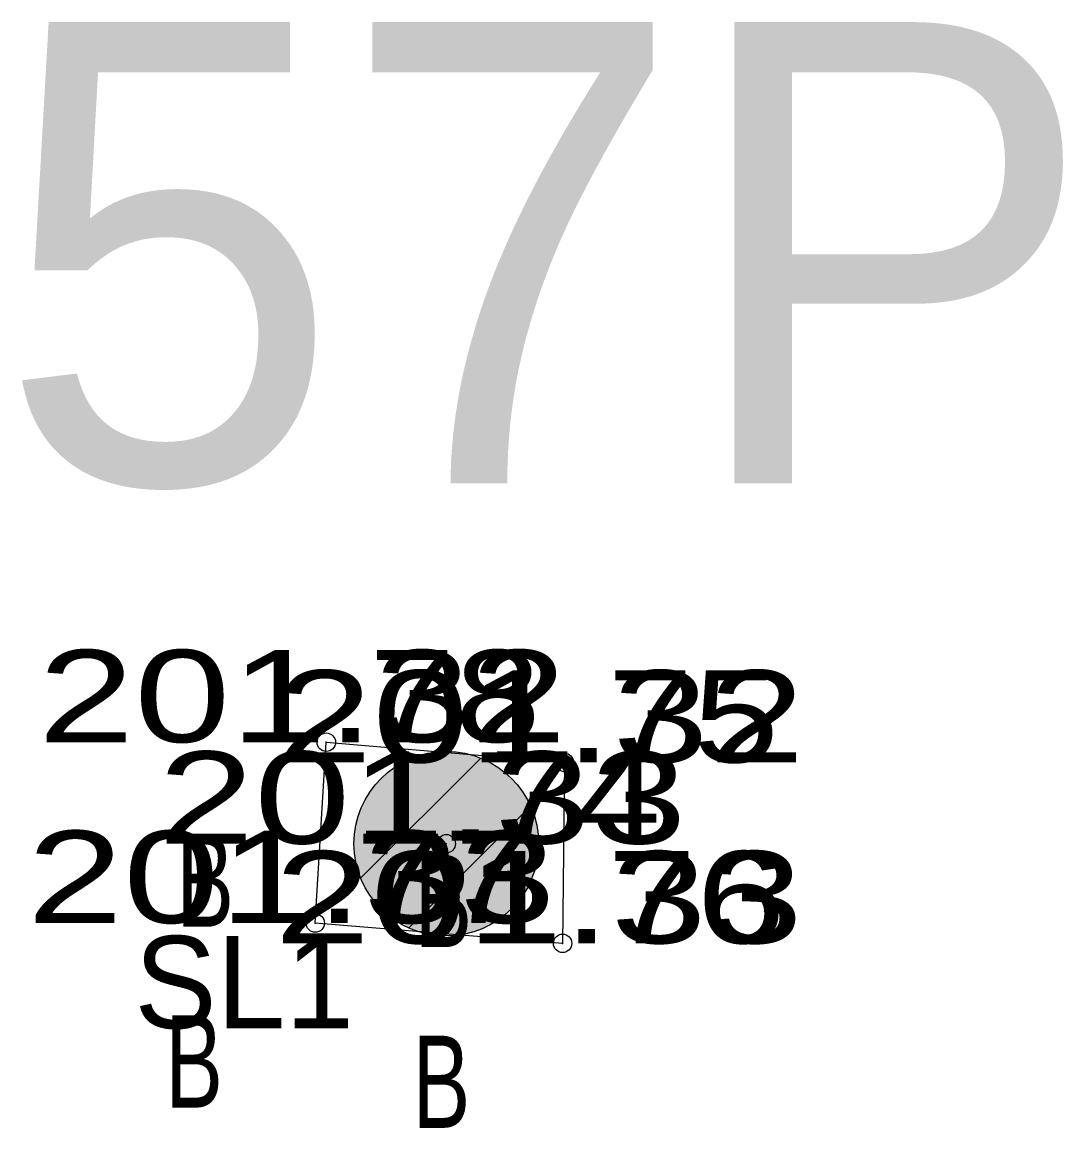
# Model space of a CAD drawing. Extents: x -466020 to -463400, y -1095586 to -1094005.
# Drawn here: x -465185.77 to -465180.13, y -1095138.81 to -1095132.82 of the extents above; entities that cross this region are included whole.
import ezdxf
from ezdxf.enums import TextEntityAlignment as Align

# ---------------------------------------------------------------- set-up
doc = ezdxf.new("R2010")
doc.units = 0
doc.header["$LTSCALE"] = 0.2
doc.header["$PDMODE"] = 32
doc.header["$PDSIZE"] = 0.1
for name, color, linetype in [('1', 7, 'Continuous'), ('2', 7, 'Continuous'), ('3', 7, 'Continuous'), ('4', 7, 'Continuous')]:
    doc.layers.add(name, color=color, linetype=linetype)
doc.layers.add('11', color=7, linetype='Continuous', lineweight=25)
doc.layers.add('12', color=7, linetype='Continuous', lineweight=25)

msp = doc.modelspace()

# ---------------------------------------------------------------- hatches: boundary and pattern name
at = {"layer": '11'}
msp.add_hatch(color=256, dxfattribs=at).paths.add_polyline_path([(-465182.97, -1095137.27, 1), (-465183.97, -1095137.27, 1)])

# ---------------------------------------------------------------- linework, layer by layer
at = {"layer": '1'}
for p in [(-465184.12, -1095136.72), (-465182.83, -1095136.83), (-465183.47, -1095137.27), (-465184.18, -1095137.7), (-465182.84, -1095137.81)]:
    msp.add_point(p, dxfattribs=at)
at = {"layer": '11'}
for p, q in [((-465183.931, -1095137.454), (-465183.285, -1095136.808)), ((-465183.671, -1095137.724), (-465183.016, -1095137.069))]:
    msp.add_line(p, q, dxfattribs=at)
msp.add_circle((-465183.47, -1095137.27), 0.5, dxfattribs=at)
at = {"layer": '12'}
msp.add_lwpolyline([(-465182.83, -1095136.83), (-465182.84, -1095137.81), (-465184.18, -1095137.7), (-465184.12, -1095136.72)], close=True, dxfattribs=at)

# ---------------------------------------------------------------- texts
at = {"layer": '11'}
msp.add_text('57P', height=2.5, dxfattribs=at).set_placement((-465182.9275, -1095135.318), align=Align.CENTER)
at = {"layer": '2'}
for s, width, p in [(' 78', 1.25, (-465184.12, -1095136.72)), (' 75', 1.25, (-465182.83, -1095136.83)), (' 74', 1.25, (-465183.47, -1095137.27)), (' 77', 1.25, (-465184.18, -1095137.7)), (' 76', 1.3, (-465182.84, -1095137.81))]:
    msp.add_text(s, height=0.5, dxfattribs=dict(at, width=width)).set_placement(p)
at = {"layer": '3', "width": 1.4}
for s, p in [('201.32 ', (-465184.1195, -1095136.72)), ('201.32 ', (-465182.8295, -1095136.83)), ('201.33 ', (-465183.4695, -1095137.27)), ('201.33 ', (-465184.1795, -1095137.7)), ('201.33 ', (-465182.8395, -1095137.81))]:
    msp.add_text(s, height=0.5, dxfattribs=at).set_placement(p, align=Align.CENTER)
at = {"layer": '4', "width": 0.7}
for p in [(-465184.62, -1095137.72), (-465183.33, -1095137.83), (-465184.68, -1095138.7), (-465183.34, -1095138.81)]:
    msp.add_text('B', height=0.5, dxfattribs=at).set_placement(p, align=Align.RIGHT)
at = {"layer": '4'}
msp.add_text('SL1', height=0.5, dxfattribs=at).set_placement((-465183.97, -1095138.27), align=Align.RIGHT)

doc.saveas('drawing.dxf')
